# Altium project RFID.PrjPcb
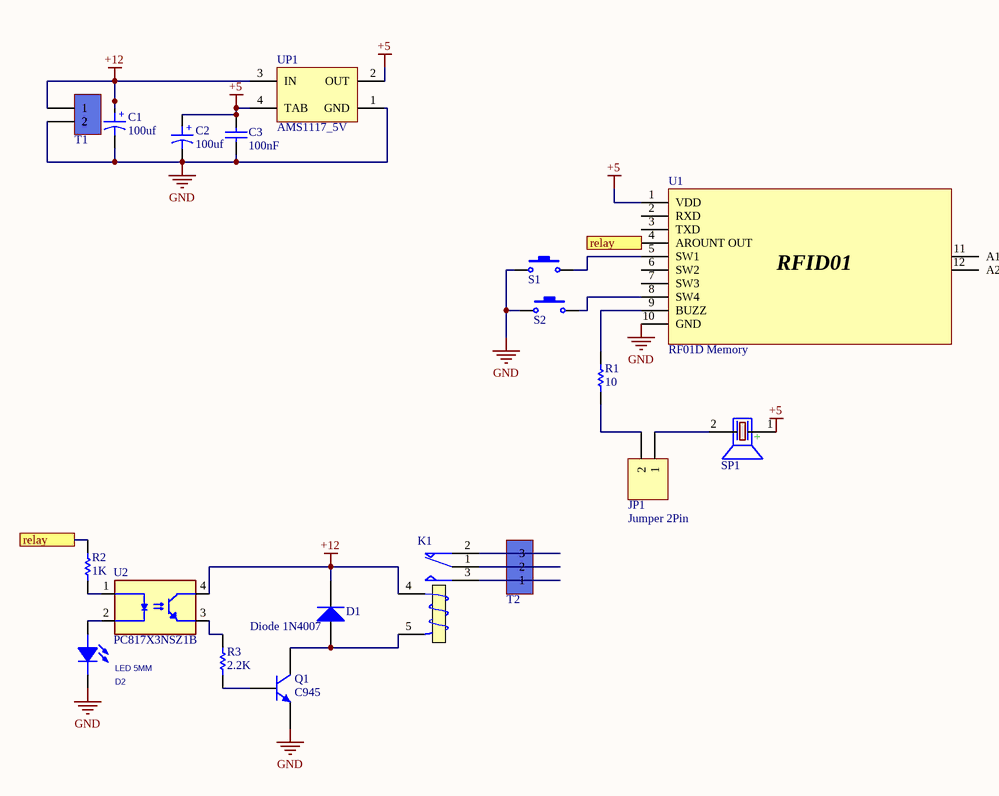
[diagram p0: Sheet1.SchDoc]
1 sheet, 19 parts. Net scope: flat (ports and power ports of the same name join across sheets).
Board file: PCB1.PcbDoc

## Sheet Sheet1.SchDoc
size A

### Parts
C1  100uf  [Cap electrolitic radial 6.3x12-2.5]
C2  100uf  [Cap electrolitic radial 6.3x12-2.5]
C3  100nF  [Cap-100nF]
D1  Diode 1N4007  [DO-41]
D2  LED 5MM  [LED5MM_GRN]
JP1  Jumper 2Pin  [Jumper Small - 2.54 - Black]
K1  (no value)  [Relay 18.85x15.35x15.70]
Q1  C945  [C945]
R1  10  [RES-(1/4)]
R2  1K  [RES-(1/4)]
R3  2.2K  [RES-(1/4)]
S1  Switch PB  [Switch - Push to On]  (value not drawn)
S2  Switch PB  [Switch - Push to On]  (value not drawn)
SP1  (no value)  [BUZZER 7.62mm DC]
T1  KF301_Terminal  [KF301 2PIN]  (value not drawn)
T2  KF301_Terminal  [KF301 3PIN]  (value not drawn)
U1  RF01D Memory  [RFID]
U2  PC817X3NSZ1B  [DIP762W50P254L495H455Q4]
UP1  AMS1117_5V  [SOT223]

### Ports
relay

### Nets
+5: C2.1 C3.2 SP1.1(+) U1.1(VDD) UP1.2(OUT) UP1.4(TAB)
+12: C1.1 D1.2(K) K1.4(T1) T1.1 U2.4(COLLECTOR) UP1.3(IN)
GND: C1.2 C2.2 C3.1 D2.2(CATHODE) Q1.1(E) S1.1 S2.1 T1.2 U1.10(GND) UP1.1(GND)
NetD1_1: D1.1(A) K1.5(T2) Q1.2(C)
NetD2_1: D2.1(ANODE) U2.2(CATHODE)
NetJP1_1: JP1.1 SP1.2(-)
NetJP1_2: JP1.2 R1.2
NetK1_1: K1.1(COM) T2.2
NetK1_2: K1.2(NC) T2.3
NetK1_3: K1.3(NO) T2.1
NetQ1_3: Q1.3(B) R3.1
NetR1_1: R1.1 U1.9(BUZZ)
NetR2_1: R2.1 U2.1(ANODE)
NetR2_2: R2.2 U1.4(AROUNT_OUT) ; port relay
NetR3_2: R3.2 U2.3(EMITTER)
NetS1_2: S1.2 U1.5(SW1)
NetS2_2: S2.2 U1.8(SW4)

Not connected (* = marked no-connect by the designer): U1 2(RXD) 3(TXD) 6(SW2) 7(SW3) 11(A1) 12(A2)

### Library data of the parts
C1 C2 = Cap ELECTROLITIC TOTAL SIZE: Cap electrolitic radial; Designer: Abbas Basereh; VALUE: 1uF
C3 = CAP CERAMIC TOTAL SIZE: CAP Ceramic Total; Designer: Ali Hafizi
D1 = Diode 1N4007: 1 Amp General Purpose Rectifier
D2 = LED 5MM: Light Emitting Diode; Designer: Abbas Basereh
JP1 = Jumper 2Pin: Jumper, 2-Pin; Designer: Abbas Basereh
K1 = RELAY_SPDT: Single-Pole Dual-Throw Relay; Designer: Abbas Basereh
Q1 = C945: NPN Transistor; Designer: Saeid Jorablo; Company: IPA CO
R1-R3 = RES DIP PACKAGE: TOTAL DIP RESISTOR PACK; Designer: Ali Hafizi
S1 S2 = Switch PB: Push Button Switch
SP1 = PIEZO BUZZER: PIEZO BUZZER ACTIVE; Designer: Abbas Basereh; Comment_1: SPEAKER AND BEEP
T1 = KF301-2Pin_Terminal: Terminal 2 Pin 250VAC 16A; Part. No: KF301 2P; Designer: Abbas Basereh
T2 = KF301-3Pin_Terminal: Terminal 3 Pin 250VAC 16A; Part. No: KF301 3P; Designer: Abbas Basereh
U1 = RFID
U2 = PC817X3NSZ1B: Optoisolator Transistor Output 1 Channel 4-DIP; MF: Sharp Microelectronics
UP1 = AMS1117-x.x: x.x Volt, 800mA Low-Dropout Linear Regulator, 4-pin SOT-223; Designer: Ali Hafizi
